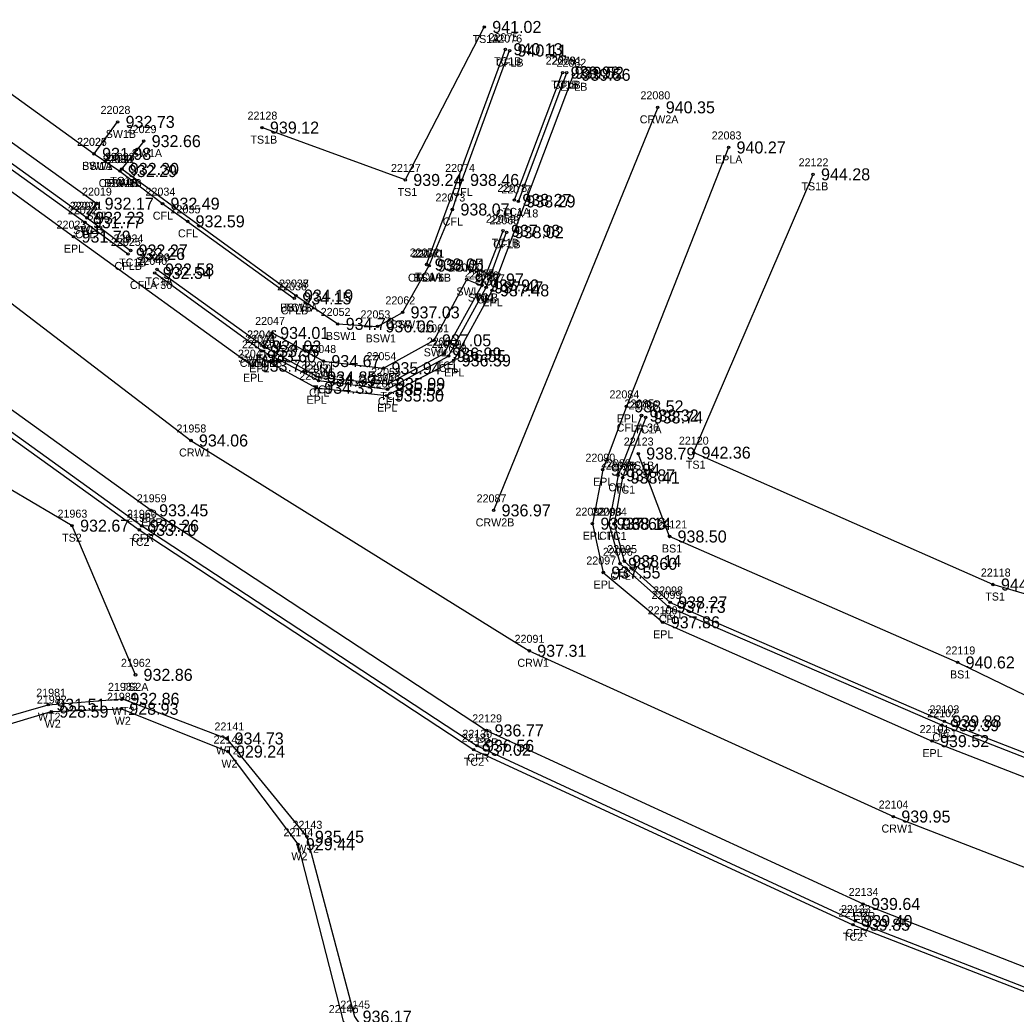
# Model space of a CAD drawing. Extents: x 1576181 to 1577685, y 1099396 to 1101490.
# Drawn here: x 1577444.3 to 1577568.7, y 1100817.4 to 1100941.6 of the extents above; entities that cross this region are included whole.
import ezdxf

# ---------------------------------------------------------------- set-up
doc = ezdxf.new("R2010")
doc.units = 0
for name, color, linetype in [('RD_DTM_BkLn1', 7, 'Continuous'), ('RD_DTM_BkLn2', 7, 'Continuous'), ('RD_DTM_BkLn_txCode', 7, 'Continuous'), ('RD_EX_BldgApp', 7, 'Continuous'), ('RD_EX_Conc', 7, 'Continuous'), ('RD_EX_Conc_txCode', 7, 'Continuous'), ('RD_EX_Misc_txCode', 7, 'Continuous'), ('RD_EX_Road', 7, 'Continuous'), ('RD_EX_Road_txCode', 7, 'Continuous'), ('RD_EX_TX_Conc_ELEV', 7, 'Continuous'), ('RD_EX_TX_Misc_ELEV', 7, 'Continuous'), ('RD_EX_TX_Road_ELEV', 7, 'Continuous'), ('RD_HC_Survey_ELEV', 7, 'Continuous'), ('RD_HC_Survey_txCode', 7, 'Continuous'), ('RD_SMD_Locator', 7, 'Continuous')]:
    doc.layers.add(name, color=color, linetype=linetype)

msp = doc.modelspace()

# ---------------------------------------------------------------- linework, layer by layer
at = {"layer": 'RD_DTM_BkLn1'}
msp.add_line((1577523.99, 1100930.7), (1577503.49, 1100880.36), dxfattribs=at)
msp.add_lwpolyline([(1577238.59, 1101054.64), (1577263.64, 1101036.24), (1577303.95, 1101006.72), (1577344.58, 1100977.95), (1577386.9, 1100948.15), (1577426.17, 1100919.26), (1577465.69, 1100889.09), (1577507.94, 1100862.82), (1577553.41, 1100842.12), (1577599.84, 1100824.14), (1577646.74, 1100805.8)], dxfattribs=at)
at = {"layer": 'RD_DTM_BkLn2'}
for p, q in [((1577495.13, 1100911.07), (1577504.97, 1100937.96)), ((1577506.08, 1100919.14), (1577512.11, 1100935.04)), ((1577457.06, 1100923.01), (1577478.81, 1100907.19))]:
    msp.add_line(p, q, dxfattribs=at)
for points in [[(1577260.56, 1101056.27), (1577271.65, 1101048), (1577312.74, 1101017.67), (1577352.97, 1100988.91), (1577392.63, 1100960.2), (1577433.92, 1100930.47), (1577452.73, 1100916.9), (1577458.15, 1100912.82)], [(1577502.32, 1100940.74), (1577492.46, 1100921.63), (1577474.56, 1100928.17)], [(1577662.62, 1100837.15), (1577614.29, 1100856.81), (1577565.85, 1100871.1), (1577528.46, 1100887.57), (1577543.38, 1100922.33)], [(1577395.54, 1100920.23), (1577401.33, 1100918.75), (1577405.58, 1100916.45), (1577417.84, 1100907.66), (1577459.24, 1100877.93), (1577501.01, 1100850.46), (1577548.36, 1100828.61), (1577593.56, 1100811.04), (1577656.23, 1100786.49)], [(1577461.46, 1100910.45), (1577474.83, 1100900.83), (1577481.72, 1100896.97), (1577490.31, 1100896.16), (1577497.33, 1100899.95), (1577502.03, 1100908.45), (1577504.67, 1100915.28)], [(1577458.77, 1100859.82), (1577450.85, 1100878.45), (1577422.9, 1100894.91), (1577386.39, 1100908)], [(1577522.49, 1100891.97), (1577519.6, 1100884.45), (1577518.53, 1100878.68), (1577519.8, 1100874.02), (1577525.54, 1100868.86), (1577559.77, 1100854.01), (1577605.06, 1100836.42), (1577651.47, 1100818.35)], [(1577658.73, 1100819.4), (1577606.88, 1100839.3), (1577561.44, 1100861.37), (1577525.46, 1100877.1), (1577521.55, 1100887.46)], [(1577432.53, 1100853.96), (1577434.36, 1100852.19), (1577447.88, 1100856.09), (1577457.13, 1100856.82), (1577470.14, 1100851.87), (1577480.17, 1100839.59), (1577486.13, 1100817.13), (1577494.64, 1100804.62), (1577509.91, 1100799.91), (1577531.35, 1100805.03), (1577541.32, 1100806.67), (1577560.38, 1100798.33), (1577576.37, 1100784.65), (1577583.76, 1100755.46)]]:
    msp.add_lwpolyline(points, dxfattribs=at)
at = {"layer": 'RD_EX_BldgApp'}
msp.add_lwpolyline([(1577431.47, 1100853.57), (1577434.21, 1100851.02), (1577448.25, 1100855.22), (1577457, 1100855.58), (1577470.32, 1100850.24), (1577479.05, 1100838.66), (1577484.72, 1100816.57), (1577493.67, 1100803.21), (1577510, 1100798.11), (1577531.96, 1100803.27), (1577542, 1100804.92), (1577559.8, 1100797.02), (1577574.7, 1100783.55), (1577581.82, 1100754.82)], dxfattribs=at)
at = {"layer": 'RD_EX_Conc'}
for p, q in [((1577506.58, 1100918.95), (1577512.62, 1100935.02)), ((1577453.6, 1100924.89), (1577456.53, 1100928.88)), ((1577459.79, 1100926.48), (1577456.82, 1100922.74))]:
    msp.add_line(p, q, dxfattribs=at)
for points in [[(1577260.09, 1101055.74), (1577271.3, 1101047.57), (1577312.39, 1101017.33), (1577352.65, 1100988.38), (1577392.28, 1100959.71), (1577433.56, 1100929.93), (1577452.44, 1100916.35), (1577457.82, 1100912.39)], [(1577352.79, 1100991.57), (1577355.36, 1100995.86), (1577382.69, 1100975.99), (1577386.31, 1100973.35), (1577395.61, 1100966.73), (1577398.83, 1100964.39), (1577422.4, 1100947.35), (1577425.71, 1100945.1), (1577453.6, 1100924.89), (1577456.82, 1100922.74)], [(1577352.79, 1100991.57), (1577393.94, 1100961.92), (1577435.2, 1100932.14), (1577453.92, 1100918.67), (1577452.73, 1100916.9)], [(1577495.44, 1100910.93), (1577498.35, 1100917.94), (1577499.55, 1100921.63), (1577505.48, 1100937.79)], [(1577456.82, 1100922.74), (1577462.14, 1100918.67), (1577465.27, 1100916.46), (1577478.6, 1100906.84)], [(1577395.74, 1100920.66), (1577401.57, 1100919.25), (1577405.99, 1100917), (1577418.29, 1100908.16), (1577459.56, 1100878.43), (1577501.42, 1100850.96), (1577548.66, 1100829.07), (1577593.79, 1100811.49), (1577656.52, 1100787)], [(1577461.17, 1100910.02), (1577474.59, 1100900.28), (1577474.59, 1100900.28), (1577481.64, 1100896.58), (1577490.24, 1100895.5), (1577497.87, 1100899.64), (1577502.56, 1100908.21), (1577505.12, 1100915.09)], [(1577478.81, 1100907.19), (1577484.02, 1100903.65), (1577488.99, 1100903.34), (1577492.12, 1100905.09), (1577495.44, 1100910.93)], [(1577474.83, 1100900.83), (1577475.83, 1100902.52), (1577482.23, 1100899.01), (1577489.74, 1100898.12), (1577496.05, 1100901.6), (1577500.13, 1100909.2), (1577502.03, 1100908.45)], [(1577521.96, 1100892.21), (1577519.03, 1100884.74), (1577517.86, 1100878.7), (1577519.28, 1100873.69), (1577525.34, 1100868.31), (1577559.49, 1100853.53), (1577604.81, 1100835.83), (1577651.29, 1100817.68)]]:
    msp.add_lwpolyline(points, dxfattribs=at)
at = {"layer": 'RD_EX_Road'}
for points in [[(1577251.26, 1101061.34), (1577255.44, 1101056.29), (1577270.08, 1101045.56), (1577310.68, 1101015.78), (1577351.28, 1100986.44), (1577391.25, 1100957.77), (1577432.13, 1100928.26), (1577451.03, 1100914.55), (1577473.4, 1100898.43), (1577474.18, 1100899.6), (1577481.34, 1100895.67), (1577490.14, 1100894.7), (1577498.51, 1100899.09), (1577503.3, 1100907.84), (1577513.46, 1100934.77)], [(1577532.83, 1100925.69), (1577520.07, 1100893.35), (1577517.12, 1100885.44), (1577515.83, 1100878.7), (1577517.19, 1100872.6), (1577524.62, 1100866.38), (1577558.24, 1100851.54), (1577603.8, 1100833.78), (1577650.48, 1100815.34)], [(1577419.5, 1100910.06), (1577460.72, 1100880.37), (1577502.61, 1100852.88), (1577549.63, 1100831.2), (1577595.43, 1100813.3), (1577657.48, 1100789.05)]]:
    msp.add_lwpolyline(points, dxfattribs=at)
at = {"layer": 'RD_SMD_Locator'}
for centre in [(1577502.32, 1100940.74), (1577504.97, 1100937.96), (1577505.48, 1100937.79), (1577512.11, 1100935.04), (1577512.62, 1100935.02), (1577513.46, 1100934.77), (1577523.99, 1100930.7), (1577456.53, 1100928.88), (1577474.56, 1100928.17), (1577459.79, 1100926.48), (1577532.83, 1100925.69), (1577453.6, 1100924.89), (1577453.6, 1100924.89), (1577457.06, 1100923.01), (1577456.82, 1100922.74), (1577456.82, 1100922.74), (1577456.82, 1100922.74), (1577543.38, 1100922.33), (1577492.46, 1100921.63), (1577499.55, 1100921.63), (1577453.92, 1100918.67), (1577462.14, 1100918.67), (1577506.08, 1100919.14), (1577506.58, 1100918.95), (1577452.73, 1100916.9), (1577452.73, 1100916.9), (1577498.35, 1100917.94), (1577452.44, 1100916.35), (1577465.27, 1100916.46), (1577451.03, 1100914.55), (1577504.67, 1100915.28), (1577505.12, 1100915.09), (1577457.82, 1100912.39), (1577458.15, 1100912.82), (1577495.13, 1100911.07), (1577495.44, 1100910.93), (1577495.44, 1100910.93), (1577461.17, 1100910.02), (1577461.46, 1100910.45), (1577500.13, 1100909.2), (1577502.03, 1100908.45), (1577502.03, 1100908.45), (1577502.56, 1100908.21), (1577478.6, 1100906.84), (1577478.81, 1100907.19), (1577478.81, 1100907.19), (1577503.3, 1100907.84), (1577492.12, 1100905.09), (1577484.02, 1100903.65), (1577488.99, 1100903.34), (1577475.83, 1100902.52), (1577474.83, 1100900.83), (1577474.83, 1100900.83), (1577496.05, 1100901.6), (1577474.18, 1100899.6), (1577474.59, 1100900.28), (1577474.59, 1100900.28), (1577497.33, 1100899.95), (1577497.87, 1100899.64), (1577473.4, 1100898.43), (1577482.23, 1100899.01), (1577489.74, 1100898.12), (1577498.51, 1100899.09), (1577481.72, 1100896.97), (1577481.34, 1100895.67), (1577481.64, 1100896.58), (1577490.31, 1100896.16), (1577490.14, 1100894.7), (1577490.24, 1100895.5), (1577520.07, 1100893.35), (1577521.96, 1100892.21), (1577522.49, 1100891.97), (1577465.69, 1100889.09), (1577521.55, 1100887.46), (1577528.46, 1100887.57), (1577517.12, 1100885.44), (1577519.03, 1100884.74), (1577519.6, 1100884.45), (1577460.72, 1100880.37), (1577503.49, 1100880.36), (1577450.85, 1100878.45), (1577459.56, 1100878.43), (1577515.83, 1100878.7), (1577517.86, 1100878.7), (1577518.53, 1100878.68), (1577459.24, 1100877.93), (1577525.46, 1100877.1), (1577519.28, 1100873.69), (1577519.8, 1100874.02), (1577517.19, 1100872.6), (1577565.85, 1100871.1), (1577525.34, 1100868.31), (1577525.54, 1100868.86), (1577524.62, 1100866.38), (1577507.94, 1100862.82), (1577561.44, 1100861.37), (1577458.77, 1100859.82), (1577447.88, 1100856.09), (1577457.13, 1100856.82), (1577448.25, 1100855.22), (1577457, 1100855.58), (1577559.49, 1100853.53), (1577559.77, 1100854.01), (1577502.61, 1100852.88), (1577470.14, 1100851.87), (1577501.42, 1100850.96), (1577558.24, 1100851.54), (1577470.32, 1100850.24), (1577501.01, 1100850.46), (1577553.41, 1100842.12), (1577480.17, 1100839.59), (1577479.05, 1100838.66), (1577549.63, 1100831.2), (1577548.36, 1100828.61), (1577548.66, 1100829.07)]:
    msp.add_circle(centre, 0.15, dxfattribs=at)

# ---------------------------------------------------------------- texts
at = {"layer": 'RD_DTM_BkLn_txCode'}
for s, p in [('TS1A', (1577500.87, 1100938.74)), ('22128', (1577472.76, 1100929.17)), ('TS1B', (1577473.12, 1100926.17)), ('22122', (1577541.58, 1100923.33)), ('22127', (1577490.67, 1100922.63)), ('TS1', (1577491.5, 1100919.63)), ('TS1B', (1577541.94, 1100920.33)), ('22120', (1577526.63, 1100888.57)), ('22123', (1577519.75, 1100888.46)), ('BS1B', (1577520.13, 1100885.46)), ('TS1', (1577527.5, 1100885.57)), ('21963', (1577449.03, 1100879.45)), ('22121', (1577523.94, 1100878.1)), ('TS2', (1577449.6, 1100876.45)), ('BS1', (1577524.51, 1100875.1)), ('22118', (1577564.34, 1100872.1)), ('TS1', (1577564.89, 1100869.1)), ('22119', (1577559.92, 1100862.37)), ('21962', (1577456.95, 1100860.82)), ('BS1', (1577560.49, 1100859.37)), ('TS2A', (1577457.04, 1100857.82))]:
    msp.add_text(s, height=1, dxfattribs=at).set_placement(p)
at = {"layer": 'RD_EX_Conc_txCode'}
for s, p in [('22075', (1577502.86, 1100938.96)), ('22076', (1577503.34, 1100938.79)), ('TC1B', (1577503.54, 1100935.96)), ('CFLB', (1577503.81, 1100935.79)), ('22079', (1577509.99, 1100936.04)), ('22081', (1577510.78, 1100936.02)), ('TC1B', (1577510.68, 1100933.04)), ('CFLB', (1577510.94, 1100933.02)), ('22028', (1577454.41, 1100929.88)), ('22029', (1577457.67, 1100927.48)), ('22026', (1577451.46, 1100925.89)), ('22027', (1577451.48, 1100925.89)), ('SW1B', (1577455.05, 1100926.88)), ('22030', (1577454.66, 1100923.74)), ('22032', (1577454.7, 1100923.74)), ('22033', (1577454.94, 1100924.01)), ('22031', (1577454.98, 1100923.74)), ('SW1A', (1577458.29, 1100924.48)), ('SW1A', (1577452.1, 1100922.89)), ('BSW1', (1577452.12, 1100922.89)), ('22074', (1577497.44, 1100922.63)), ('TC1A', (1577455.61, 1100921.01)), ('22019', (1577452.09, 1100919.67)), ('CFLA 6', (1577454.17, 1100920.74)), ('BSW1B', (1577454.87, 1100920.74)), ('SW1B', (1577455.34, 1100920.74)), ('22034', (1577460.02, 1100919.67)), ('CFL', (1577498.35, 1100919.63)), ('22078', (1577503.96, 1100920.14)), ('22077', (1577504.46, 1100919.95)), ('22073', (1577496.23, 1100918.94)), ('22022', (1577450.32, 1100917.35)), ('22020', (1577450.57, 1100917.9)), ('22021', (1577450.9, 1100917.9)), ('22035', (1577463.15, 1100917.46)), ('TC1A', (1577504.63, 1100917.14)), ('SWL', (1577452.63, 1100916.67)), ('CFL', (1577460.93, 1100916.67)), ('CFL', (1577497.14, 1100915.94)), ('22069', (1577502.53, 1100916.28)), ('22068', (1577502.97, 1100916.09)), ('CFLA 18', (1577503.79, 1100916.95)), ('SWLB', (1577450.97, 1100914.9)), ('TC1', (1577451.77, 1100914.9)), ('CFL', (1577451.23, 1100914.35)), ('22025', (1577455.7, 1100913.39)), ('22024', (1577456.03, 1100913.82)), ('CFL', (1577464.07, 1100914.46)), ('TC1B', (1577503.24, 1100913.28)), ('CFLB', (1577503.44, 1100913.09)), ('22040', (1577459.01, 1100911.02)), ('22039', (1577459.34, 1100911.45)), ('22072', (1577493.01, 1100912.07)), ('22070', (1577493.28, 1100911.93)), ('22071', (1577493.6, 1100911.93)), ('CFLB', (1577456.14, 1100910.39)), ('TC1B', (1577456.72, 1100910.82)), ('22063', (1577497.99, 1100910.2)), ('TC1A', (1577460.01, 1100908.45)), ('CFLA 6', (1577492.79, 1100908.93)), ('BSW1B', (1577493.49, 1100908.93)), ('TC1A', (1577493.68, 1100909.07)), ('22064', (1577499.89, 1100909.45)), ('22065', (1577499.89, 1100909.45)), ('22066', (1577500.4, 1100909.21)), ('CFLA 36', (1577458.07, 1100908.02)), ('22036', (1577476.46, 1100907.84)), ('22037', (1577476.69, 1100908.19)), ('22038', (1577476.69, 1100908.19)), ('SWL', (1577498.84, 1100907.2)), ('22062', (1577489.98, 1100906.09)), ('SWLB', (1577500.27, 1100906.45)), ('TC1', (1577501.07, 1100906.45)), ('CFL', (1577501.36, 1100906.21)), ('BSW1A', (1577476.84, 1100905.19)), ('CFLB', (1577476.92, 1100904.84)), ('TC1B', (1577477.37, 1100905.19)), ('22052', (1577481.9, 1100904.65)), ('22047', (1577473.71, 1100903.52)), ('22053', (1577486.87, 1100904.34)), ('BSW1', (1577490.64, 1100903.09)), ('22061', (1577494.2, 1100902.6)), ('22043', (1577472.47, 1100901.28)), ('22044', (1577472.47, 1100901.28)), ('22046', (1577472.69, 1100901.83)), ('22045', (1577472.71, 1100901.83)), ('BSW1', (1577482.54, 1100901.65)), ('BSW1', (1577487.51, 1100901.34)), ('22060', (1577495.15, 1100900.95)), ('SWL', (1577474.54, 1100900.52)), ('22048', (1577480.11, 1100900.01)), ('22059', (1577495.75, 1100900.64)), ('SWLA 60', (1577471.6, 1100898.83)), ('TC1', (1577473.87, 1100898.83)), ('22054', (1577487.62, 1100899.12)), ('SWL', (1577494.76, 1100899.6)), ('CFLA 18', (1577471.79, 1100898.28)), ('CFLB', (1577472.91, 1100898.28)), ('22050', (1577479.49, 1100897.58)), ('22051', (1577479.89, 1100897.97)), ('TC1', (1577496.37, 1100897.95)), ('CFL', (1577496.66, 1100897.64)), ('SWL', (1577480.94, 1100897.01)), ('22056', (1577488.1, 1100896.5)), ('22055', (1577488.2, 1100897.16)), ('SWL', (1577488.45, 1100896.12)), ('TC1', (1577480.76, 1100894.97)), ('CFL', (1577480.44, 1100894.58)), ('CFL', (1577489.04, 1100893.5)), ('TC1', (1577489.35, 1100894.16)), ('22085', (1577519.84, 1100893.21)), ('22086', (1577520.35, 1100892.97)), ('CFLA 36', (1577518.86, 1100890.21)), ('TC1A', (1577521.05, 1100889.97)), ('22089', (1577516.91, 1100885.74)), ('22088', (1577517.48, 1100885.45)), ('CFL', (1577517.82, 1100882.74)), ('TC1', (1577518.64, 1100882.45)), ('21960', (1577457.7, 1100879.43)), ('21961', (1577457.71, 1100878.93)), ('22093', (1577515.75, 1100879.7)), ('22094', (1577516.41, 1100879.68)), ('CFR', (1577458.33, 1100876.43)), ('CFL', (1577516.66, 1100876.7)), ('TC1', (1577517.57, 1100876.68)), ('TC2', (1577458, 1100875.93)), ('22095', (1577517.68, 1100875.02)), ('22096', (1577517.14, 1100874.69)), ('CFL', (1577518.08, 1100871.69)), ('TC1', (1577518.84, 1100872.02)), ('22098', (1577523.42, 1100869.86)), ('22099', (1577523.22, 1100869.31)), ('CFL', (1577524.13, 1100866.31)), ('TC1', (1577524.58, 1100866.86)), ('22103', (1577557.93, 1100855.01)), ('22102', (1577557.65, 1100854.53)), ('22131', (1577499.5, 1100851.46)), ('22130', (1577499.59, 1100851.96)), ('CFL', (1577558.28, 1100851.53)), ('TC1', (1577558.81, 1100852.01)), ('CFR', (1577500.2, 1100848.96)), ('TC2', (1577499.77, 1100848.46)), ('22133', (1577546.87, 1100830.07)), ('22132', (1577546.56, 1100829.61)), ('TC2', (1577547.11, 1100826.61)), ('CFR', (1577547.44, 1100827.07))]:
    msp.add_text(s, height=1, dxfattribs=at).set_placement(p)
at = {"layer": 'RD_EX_Misc_txCode'}
for s, p in [('21983', (1577455.33, 1100857.82)), ('21981', (1577446.37, 1100857.09)), ('21982', (1577446.45, 1100856.22)), ('21984', (1577455.2, 1100856.58)), ('WT2', (1577446.58, 1100854.09)), ('WT2', (1577455.82, 1100854.82)), ('W2', (1577447.43, 1100853.22)), ('W2', (1577456.18, 1100853.58)), ('22141', (1577468.63, 1100852.87)), ('22142', (1577468.52, 1100851.24)), ('WT2', (1577468.83, 1100849.87)), ('W2', (1577469.5, 1100848.24)), ('22143', (1577478.38, 1100840.59)), ('22144', (1577477.25, 1100839.66)), ('WT2', (1577478.86, 1100837.59)), ('W2', (1577478.23, 1100836.66)), ('22146', (1577482.9, 1100817.57)), ('22145', (1577484.34, 1100818.13))]:
    msp.add_text(s, height=1, dxfattribs=at).set_placement(p)
at = {"layer": 'RD_EX_Road_txCode'}
for s, p in [('22082', (1577511.34, 1100935.77)), ('EPLB', (1577511.78, 1100932.77)), ('22083', (1577530.72, 1100926.69)), ('EPLA', (1577531.14, 1100923.69)), ('22023', (1577448.91, 1100915.55)), ('EPL', (1577449.82, 1100912.55)), ('22067', (1577501.16, 1100908.84)), ('EPL', (1577502.09, 1100905.84)), ('22042', (1577472.06, 1100900.6)), ('22058', (1577496.39, 1100900.09)), ('22041', (1577471.56, 1100899.43)), ('EPL', (1577472.97, 1100897.6)), ('EPL', (1577472.19, 1100896.43)), ('22049', (1577479.22, 1100896.67)), ('EPL', (1577497.31, 1100897.09)), ('22057', (1577488.02, 1100895.7)), ('EPL', (1577480.13, 1100893.67)), ('22084', (1577517.96, 1100894.35)), ('EPL', (1577488.94, 1100892.7)), ('EPL', (1577518.87, 1100891.35)), ('22090', (1577514.96, 1100886.44)), ('EPL', (1577515.91, 1100883.44)), ('21959', (1577458.93, 1100881.37)), ('22092', (1577513.71, 1100879.7)), ('EPR', (1577459.49, 1100878.37)), ('EPL', (1577514.62, 1100876.7)), ('22097', (1577515.07, 1100873.6)), ('EPL', (1577515.98, 1100870.6)), ('22100', (1577522.74, 1100867.38)), ('EPL', (1577523.41, 1100864.38)), ('22129', (1577500.82, 1100853.88)), ('22101', (1577556.69, 1100852.54)), ('EPR', (1577501.38, 1100850.88)), ('EPL', (1577557.04, 1100849.54)), ('22134', (1577547.83, 1100832.2)), ('EPR', (1577548.4, 1100829.2))]:
    msp.add_text(s, height=1, dxfattribs=at).set_placement(p)
at = {"layer": 'RD_EX_TX_Conc_ELEV'}
for s, p in [('940.13', (1577505.97, 1100937.21)), ('940.11', (1577506.48, 1100937.04)), ('939.98', (1577513.11, 1100934.29)), ('939.52', (1577513.62, 1100934.27)), ('932.73', (1577457.53, 1100928.13)), ('932.66', (1577460.79, 1100925.73)), ('931.98', (1577454.6, 1100924.14)), ('931.98', (1577454.6, 1100924.14)), ('932.29', (1577457.82, 1100921.99)), ('932.29', (1577457.82, 1100921.99)), ('932.29', (1577457.82, 1100921.99)), ('932.30', (1577458.06, 1100922.26)), ('938.46', (1577500.55, 1100920.88)), ('932.17', (1577454.92, 1100917.92)), ('932.49', (1577463.14, 1100917.92)), ('938.27', (1577507.08, 1100918.39)), ('938.29', (1577507.58, 1100918.2)), ('938.07', (1577499.35, 1100917.19)), ('931.77', (1577453.44, 1100915.6)), ('932.23', (1577453.73, 1100916.15)), ('932.23', (1577453.73, 1100916.15)), ('932.59', (1577466.27, 1100915.71)), ('937.98', (1577505.67, 1100914.53)), ('938.02', (1577506.12, 1100914.34)), ('932.26', (1577458.82, 1100911.64)), ('932.27', (1577459.15, 1100912.07)), ('932.54', (1577462.17, 1100909.27)), ('932.58', (1577462.46, 1100909.7)), ('938.05', (1577496.13, 1100910.32)), ('938.01', (1577496.44, 1100910.18)), ('938.01', (1577496.44, 1100910.18)), ('937.97', (1577501.13, 1100908.45)), ('937.92', (1577503.03, 1100907.7)), ('937.92', (1577503.03, 1100907.7)), ('937.47', (1577503.56, 1100907.46)), ('934.15', (1577479.6, 1100906.09)), ('934.19', (1577479.81, 1100906.44)), ('934.19', (1577479.81, 1100906.44)), ('937.03', (1577493.12, 1100904.34)), ('934.76', (1577485.02, 1100902.9)), ('934.01', (1577476.83, 1100901.77)), ('936.06', (1577489.99, 1100902.59)), ('937.05', (1577497.05, 1100900.85)), ('933.55', (1577475.59, 1100899.53)), ('933.55', (1577475.59, 1100899.53)), ('934.03', (1577475.83, 1100900.08)), ('934.03', (1577475.83, 1100900.08)), ('936.99', (1577498.33, 1100899.2)), ('934.67', (1577483.23, 1100898.26)), ('936.55', (1577498.87, 1100898.89)), ('935.94', (1577490.74, 1100897.37)), ('934.39', (1577482.64, 1100895.83)), ('934.85', (1577482.72, 1100896.22)), ('935.52', (1577491.24, 1100894.75)), ('935.99', (1577491.31, 1100895.41)), ('938.32', (1577522.96, 1100891.46)), ('938.74', (1577523.49, 1100891.22)), ('937.87', (1577520.03, 1100883.99)), ('938.41', (1577520.6, 1100883.7)), ('933.70', (1577460.24, 1100877.18)), ('933.26', (1577460.56, 1100877.68)), ('937.66', (1577518.86, 1100877.95)), ('938.14', (1577519.53, 1100877.93)), ('938.14', (1577520.8, 1100873.27)), ('937.60', (1577520.28, 1100872.94)), ('938.27', (1577526.54, 1100868.11)), ('937.73', (1577526.34, 1100867.56)), ('939.88', (1577560.77, 1100853.26)), ('939.39', (1577560.49, 1100852.78)), ('937.02', (1577502.01, 1100849.71)), ('936.56', (1577502.42, 1100850.21)), ('939.40', (1577549.66, 1100828.32)), ('939.85', (1577549.36, 1100827.86))]:
    msp.add_text(s, height=1.5, dxfattribs=at).set_placement(p)
at = {"layer": 'RD_EX_TX_Misc_ELEV'}
for s, p in [('941.02', (1577503.32, 1100939.99)), ('939.12', (1577475.56, 1100927.42)), ('944.28', (1577544.38, 1100921.58)), ('939.24', (1577493.46, 1100920.88)), ('942.36', (1577529.46, 1100886.82)), ('938.79', (1577522.55, 1100886.71)), ('932.67', (1577451.85, 1100877.7)), ('938.50', (1577526.46, 1100876.35)), ('944.71', (1577566.85, 1100870.35)), ('940.62', (1577562.44, 1100860.62)), ('932.86', (1577459.77, 1100859.07)), ('932.86', (1577458.13, 1100856.07)), ('931.51', (1577448.88, 1100855.34)), ('928.59', (1577449.25, 1100854.47)), ('928.93', (1577458, 1100854.83)), ('934.73', (1577471.14, 1100851.12)), ('929.24', (1577471.32, 1100849.49)), ('935.45', (1577481.17, 1100838.84)), ('929.44', (1577480.05, 1100837.91)), ('936.17', (1577487.13, 1100816.38))]:
    msp.add_text(s, height=1.5, dxfattribs=at).set_placement(p)
at = {"layer": 'RD_EX_TX_Road_ELEV'}
for s, p in [('939.56', (1577514.46, 1100934.02)), ('940.27', (1577533.83, 1100924.94)), ('931.79', (1577452.03, 1100913.8)), ('937.48', (1577504.3, 1100907.09)), ('933.60', (1577475.18, 1100898.85)), ('936.59', (1577499.51, 1100898.34)), ('933.71', (1577474.4, 1100897.68)), ('934.33', (1577482.34, 1100894.92)), ('935.50', (1577491.14, 1100893.95)), ('938.52', (1577521.07, 1100892.6)), ('937.94', (1577518.12, 1100884.69)), ('933.45', (1577461.72, 1100879.62)), ('937.68', (1577516.83, 1100877.95)), ('937.55', (1577518.19, 1100871.85)), ('937.86', (1577525.62, 1100865.63)), ('936.77', (1577503.61, 1100852.13)), ('939.52', (1577559.24, 1100850.79)), ('939.64', (1577550.63, 1100830.45))]:
    msp.add_text(s, height=1.5, dxfattribs=at).set_placement(p)
at = {"layer": 'RD_HC_Survey_ELEV'}
for s, p in [('940.35', (1577524.99, 1100929.95)), ('934.06', (1577466.69, 1100888.34)), ('936.97', (1577504.49, 1100879.61)), ('937.31', (1577508.94, 1100862.07)), ('939.95', (1577554.41, 1100841.37))]:
    msp.add_text(s, height=1.5, dxfattribs=at).set_placement(p)
at = {"layer": 'RD_HC_Survey_txCode'}
for s, p in [('22080', (1577521.83, 1100931.7)), ('CRW2A', (1577521.74, 1100928.7)), ('21958', (1577463.89, 1100890.09)), ('CRW1', (1577464.21, 1100887.09)), ('22087', (1577501.37, 1100881.36)), ('CRW2B', (1577501.25, 1100878.36)), ('22091', (1577506.11, 1100863.82)), ('CRW1', (1577506.46, 1100860.82)), ('22104', (1577551.58, 1100843.12)), ('CRW1', (1577551.93, 1100840.12))]:
    msp.add_text(s, height=1, dxfattribs=at).set_placement(p)

doc.saveas('drawing.dxf')
